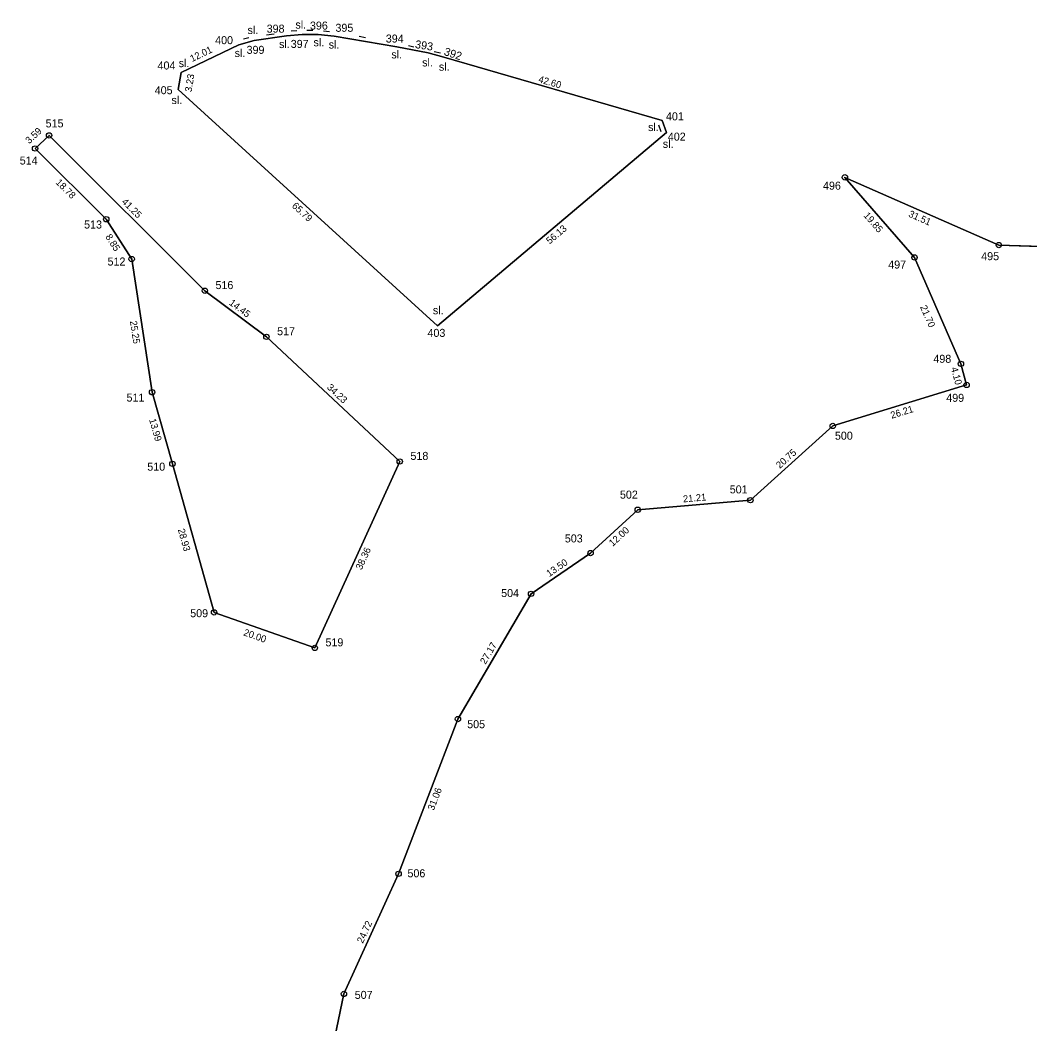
# Model space of a CAD drawing. Extents: x -555170 to -550532, y -1039598 to -1034701.
# Drawn here: x -554680.5 to -554491.3, y -1037842.9 to -1037655 of the extents above; entities that cross this region are included whole.
import ezdxf

# ---------------------------------------------------------------- set-up
doc = ezdxf.new("R2010")
doc.units = 0
for name, color, linetype in [('Vrstva 10', 7, 'Continuous'), ('Vrstva 40', 7, 'Continuous'), ('Vrstva 43', 7, 'Continuous'), ('Vrstva 48', 7, 'Continuous')]:
    doc.layers.add(name, color=color, linetype=linetype)

msp = doc.modelspace()

# ---------------------------------------------------------------- linework, layer by layer
at = {"layer": 'Vrstva 10'}
for p, q in [((-554628.65, -1037657.03), (-554629.67, -1037657.09)), ((-554625.63, -1037656.97), (-554626.76, -1037656.97)), ((-554622.48, -1037657.24), (-554623.65, -1037657.11)), ((-554637.62, -1037658.34), (-554638.61, -1037658.59)), ((-554632.88, -1037657.66), (-554634.28, -1037657.85)), ((-554616.95, -1037658.04), (-554615.74, -1037658.28)), ((-554607.71, -1037659.79), (-554606.7, -1037660)), ((-554602.87, -1037660.9), (-554601.74, -1037661.16)), ((-554560.84, -1037674.63), (-554560.42, -1037675.86))]:
    msp.add_line(p, q, dxfattribs=at)
at = {"layer": 'Vrstva 40'}
for p, q in [((-554636.61, -1037658.83), (-554639.47, -1037659.62)), ((-554630.58, -1037657.95), (-554636.61, -1037658.83)), ((-554627.61, -1037657.69), (-554630.58, -1037657.95)), ((-554624.62, -1037657.74), (-554627.61, -1037657.69)), ((-554621.62, -1037657.99), (-554624.62, -1037657.74)), ((-554609.88, -1037660.03), (-554621.62, -1037657.99)), ((-554639.47, -1037659.62), (-554650.32, -1037664.84)), ((-554604, -1037661.17), (-554609.88, -1037660.03)), ((-554601.06, -1037661.93), (-554604, -1037661.17)), ((-554560.2, -1037673.84), (-554601.06, -1037661.93)), ((-554650.32, -1037664.84), (-554650.84, -1037668.03)), ((-554650.84, -1037668.03), (-554602.26, -1037712.22)), ((-554559.4, -1037676.04), (-554560.2, -1037673.84)), ((-554602.26, -1037712.22), (-554559.4, -1037676.04)), ((-554675.05, -1037676.6), (-554677.67, -1037679.05)), ((-554645.87, -1037705.67), (-554675.05, -1037676.6)), ((-554677.67, -1037679.05), (-554664.33, -1037692.29)), ((-554497.11, -1037697.13), (-554525.95, -1037684.45)), ((-554525.95, -1037684.45), (-554512.91, -1037699.45)), ((-554664.33, -1037692.29), (-554659.57, -1037699.74)), ((-554453.05, -1037698.58), (-554497.11, -1037697.13)), ((-554659.57, -1037699.74), (-554655.75, -1037724.68)), ((-554512.91, -1037699.45), (-554504.21, -1037719.35)), ((-554634.32, -1037714.31), (-554645.87, -1037705.67)), ((-554609.34, -1037737.65), (-554634.32, -1037714.31)), ((-554504.21, -1037719.35), (-554503.14, -1037723.31)), ((-554503.14, -1037723.31), (-554528.22, -1037731)), ((-554655.75, -1037724.68), (-554651.93, -1037738.08)), ((-554528.22, -1037731), (-554543.65, -1037744.89)), ((-554651.93, -1037738.08), (-554644.13, -1037765.9)), ((-554625.26, -1037772.55), (-554609.34, -1037737.65)), ((-554543.65, -1037744.89), (-554564.77, -1037746.69)), ((-554564.77, -1037746.69), (-554573.59, -1037754.79)), ((-554573.59, -1037754.79), (-554584.74, -1037762.42)), ((-554584.74, -1037762.42), (-554598.45, -1037785.86)), ((-554644.13, -1037765.9), (-554625.26, -1037772.55)), ((-554598.45, -1037785.86), (-554609.57, -1037814.85)), ((-554609.57, -1037814.85), (-554619.81, -1037837.33)), ((-554619.81, -1037837.33), (-554624.63, -1037860.46))]:
    msp.add_line(p, q, dxfattribs=at)
at = {"layer": 'Vrstva 43'}
for p, q in [((-554636.61, -1037658.83), (-554636.61, -1037658.83)), ((-554630.58, -1037657.95), (-554630.58, -1037657.95)), ((-554627.61, -1037657.69), (-554627.61, -1037657.69)), ((-554624.62, -1037657.74), (-554624.62, -1037657.74)), ((-554621.62, -1037657.99), (-554621.62, -1037657.99)), ((-554639.47, -1037659.62), (-554639.47, -1037659.62)), ((-554609.88, -1037660.03), (-554609.88, -1037660.03)), ((-554604, -1037661.17), (-554604, -1037661.17)), ((-554601.06, -1037661.93), (-554601.06, -1037661.93)), ((-554650.32, -1037664.84), (-554650.32, -1037664.84)), ((-554650.84, -1037668.03), (-554650.84, -1037668.03)), ((-554560.2, -1037673.84), (-554560.2, -1037673.84)), ((-554559.4, -1037676.04), (-554559.4, -1037676.04)), ((-554675.05, -1037676.6), (-554675.05, -1037676.6)), ((-554677.67, -1037679.05), (-554677.67, -1037679.05)), ((-554525.95, -1037684.45), (-554525.95, -1037684.45)), ((-554664.33, -1037692.29), (-554664.33, -1037692.29)), ((-554497.11, -1037697.13), (-554497.11, -1037697.13)), ((-554659.57, -1037699.74), (-554659.57, -1037699.74)), ((-554512.91, -1037699.45), (-554512.91, -1037699.45)), ((-554645.87, -1037705.67), (-554645.87, -1037705.67)), ((-554602.26, -1037712.22), (-554602.26, -1037712.22)), ((-554634.32, -1037714.31), (-554634.32, -1037714.31)), ((-554504.21, -1037719.35), (-554504.21, -1037719.35)), ((-554503.14, -1037723.31), (-554503.14, -1037723.31)), ((-554655.75, -1037724.68), (-554655.75, -1037724.68)), ((-554528.22, -1037731), (-554528.22, -1037731)), ((-554651.93, -1037738.08), (-554651.93, -1037738.08)), ((-554609.34, -1037737.65), (-554609.34, -1037737.65)), ((-554543.65, -1037744.89), (-554543.65, -1037744.89)), ((-554564.77, -1037746.69), (-554564.77, -1037746.69)), ((-554573.59, -1037754.79), (-554573.59, -1037754.79)), ((-554584.74, -1037762.42), (-554584.74, -1037762.42)), ((-554644.13, -1037765.9), (-554644.13, -1037765.9)), ((-554625.26, -1037772.55), (-554625.26, -1037772.55)), ((-554598.45, -1037785.86), (-554598.45, -1037785.86)), ((-554609.57, -1037814.85), (-554609.57, -1037814.85)), ((-554619.81, -1037837.33), (-554619.81, -1037837.33))]:
    msp.add_line(p, q, dxfattribs=at)
for centre, radius in [((-554675.05, -1037676.6), 0.5), ((-554675.05, -1037676.6), 0.01), ((-554677.67, -1037679.05), 0.5), ((-554677.67, -1037679.05), 0.01), ((-554525.95, -1037684.45), 0.5), ((-554525.95, -1037684.45), 0.01), ((-554664.33, -1037692.29), 0.5), ((-554664.33, -1037692.29), 0.01), ((-554497.11, -1037697.13), 0.5), ((-554497.11, -1037697.13), 0.01), ((-554659.57, -1037699.74), 0.5), ((-554659.57, -1037699.74), 0.01), ((-554512.91, -1037699.45), 0.5), ((-554512.91, -1037699.45), 0.01), ((-554645.87, -1037705.67), 0.5), ((-554645.87, -1037705.67), 0.01), ((-554634.32, -1037714.31), 0.5), ((-554634.32, -1037714.31), 0.01), ((-554504.21, -1037719.36), 0.5), ((-554504.21, -1037719.36), 0.01), ((-554503.14, -1037723.31), 0.5), ((-554503.14, -1037723.31), 0.01), ((-554655.75, -1037724.68), 0.5), ((-554655.75, -1037724.68), 0.01), ((-554528.22, -1037731), 0.5), ((-554528.22, -1037731), 0.01), ((-554651.93, -1037738.08), 0.5), ((-554651.93, -1037738.08), 0.01), ((-554609.34, -1037737.65), 0.5), ((-554609.34, -1037737.65), 0.01), ((-554564.77, -1037746.69), 0.5), ((-554543.65, -1037744.89), 0.5), ((-554543.65, -1037744.89), 0.01), ((-554564.77, -1037746.69), 0.01), ((-554573.59, -1037754.79), 0.5), ((-554573.59, -1037754.79), 0.01), ((-554584.74, -1037762.42), 0.5), ((-554584.74, -1037762.42), 0.01), ((-554644.13, -1037765.9), 0.5), ((-554644.13, -1037765.9), 0.01), ((-554625.26, -1037772.55), 0.5), ((-554625.26, -1037772.55), 0.01), ((-554598.45, -1037785.86), 0.5), ((-554598.45, -1037785.86), 0.01), ((-554609.57, -1037814.85), 0.5), ((-554609.57, -1037814.85), 0.01), ((-554619.81, -1037837.33), 0.5), ((-554619.81, -1037837.33), 0.01)]:
    msp.add_circle(centre, radius, dxfattribs=at)
at = {"layer": 'Vrstva 48'}
for points in [[(-554559.4, -1037676.04), (-554602.26, -1037712.22), (-554650.84, -1037668.03), (-554650.32, -1037664.84), (-554639.47, -1037659.62), (-554636.61, -1037658.83), (-554630.58, -1037657.95), (-554627.61, -1037657.69), (-554624.62, -1037657.74), (-554621.62, -1037657.99), (-554609.88, -1037660.03), (-554604, -1037661.17), (-554601.06, -1037661.93), (-554560.2, -1037673.84), (-554559.4, -1037676.04)], [(-554677.67, -1037679.05), (-554675.05, -1037676.6), (-554645.87, -1037705.67), (-554634.32, -1037714.31), (-554609.34, -1037737.65), (-554625.26, -1037772.55), (-554644.13, -1037765.9), (-554651.93, -1037738.08), (-554655.75, -1037724.68), (-554659.57, -1037699.74), (-554664.33, -1037692.29), (-554677.67, -1037679.05)], [(-554624.63, -1037860.46), (-554619.81, -1037837.33), (-554609.57, -1037814.85), (-554598.45, -1037785.86), (-554584.74, -1037762.42), (-554573.59, -1037754.79), (-554564.77, -1037746.69), (-554543.65, -1037744.89), (-554528.22, -1037731), (-554503.14, -1037723.31), (-554504.21, -1037719.35), (-554512.91, -1037699.45), (-554525.95, -1037684.45), (-554497.11, -1037697.13), (-554453.05, -1037698.58)]]:
    msp.add_lwpolyline(points, dxfattribs=at)

# ---------------------------------------------------------------- texts
at = {"layer": 'Vrstva 10'}
for s, rotation, p in [('12.01', 25.6925, (-554648.26, -1037662.88)), ('3.23', 80.7417, (-554648.35, -1037668.55)), ('42.60', 343.7495, (-554583.48, -1037666.63)), ('3.59', 42.9743, (-554678.76, -1037678.26)), ('18.78', 315.2051, (-554673.92, -1037685.52)), ('41.25', 315.1011, (-554661.53, -1037689.15)), ('65.79', 317.7093, (-554629.65, -1037689.94)), ('19.85', 310.993, (-554522.53, -1037691.65)), ('31.51', 336.259, (-554514.15, -1037691.76)), ('8.85', 302.6109, (-554664.55, -1037695.58)), ('56.13', 40.1692, (-554581.25, -1037697.04)), ('14.45', 323.2228, (-554641.43, -1037708.18)), ('21.70', 293.6041, (-554511.89, -1037708.72)), ('25.25', 278.6999, (-554659.9, -1037711.39)), ('4.10', 285.0804, (-554506.1, -1037720.16)), ('34.23', 316.9368, (-554623.09, -1037723.91)), ('26.21', 17.0357, (-554517.17, -1037729.65)), ('13.99', 285.9074, (-554656.32, -1037729.81)), ('20.75', 42.0111, (-554538.14, -1037739.06)), ('21.21', 4.8668, (-554556.22, -1037745.31)), ('12.00', 42.6039, (-554569.44, -1037753.63)), ('28.93', 285.6616, (-554650.93, -1037750.4)), ('38.36', 65.4845, (-554616.5, -1037758.05)), ('13.50', 34.3697, (-554581.33, -1037759.3)), ('20.00', 340.5953, (-554638.73, -1037770.17)), ('27.17', 59.6813, (-554593.28, -1037775.73)), ('31.06', 69.0015, (-554602.97, -1037803.08)), ('24.72', 65.5193, (-554616.26, -1037827.96))]:
    msp.add_text(s, height=1.3, rotation=rotation, dxfattribs=at).set_placement(p)
at = {"layer": 'Vrstva 43'}
for s, p in [('sl.', (-554628.89, -1037656.61)), ('396', (-554626.17, -1037656.79)), ('sl.', (-554637.86, -1037657.62)), ('398', (-554634.28, -1037657.36)), ('395', (-554621.39, -1037657.2)), ('400', (-554643.93, -1037659.52)), ('sl.', (-554631.96, -1037660.25)), ('397', (-554629.77, -1037660.22)), ('sl.', (-554625.5, -1037659.92)), ('sl.', (-554622.65, -1037660.34)), ('394', (-554611.96, -1037659.22)), ('sl.', (-554640.28, -1037661.93)), ('399', (-554638.04, -1037661.33)), ('sl.', (-554610.92, -1037662.19)), ('404', (-554654.72, -1037664.26)), ('sl.', (-554650.76, -1037663.82)), ('sl.', (-554605.15, -1037663.69)), ('sl.', (-554602.01, -1037664.49)), ('405', (-554655.25, -1037668.89)), ('sl.', (-554652.11, -1037670.73)), ('401', (-554559.47, -1037673.78)), ('515', (-554675.69, -1037675.1)), ('sl.', (-554562.82, -1037675.79)), ('402', (-554559.12, -1037677.58)), ('sl.', (-554560.06, -1037678.93)), ('514', (-554680.54, -1037682.05)), ('496', (-554530.05, -1037686.76)), ('513', (-554668.48, -1037694.03)), ('495', (-554500.41, -1037699.96)), ('512', (-554664.09, -1037700.96)), ('497', (-554517.83, -1037701.53)), ('516', (-554643.87, -1037705.37)), ('sl.', (-554603.14, -1037710.08)), ('517', (-554632.32, -1037714.01)), ('403', (-554604.15, -1037714.32)), ('498', (-554509.37, -1037719.17)), ('511', (-554660.53, -1037726.43)), ('499', (-554506.96, -1037726.48)), ('500', (-554527.82, -1037733.57)), ('518', (-554607.34, -1037737.35)), ('510', (-554656.64, -1037739.37)), ('501', (-554547.52, -1037743.62)), ('502', (-554568.09, -1037744.6)), ('503', (-554578.42, -1037752.8)), ('504', (-554590.35, -1037763.03)), ('509', (-554648.6, -1037766.8)), ('519', (-554623.26, -1037772.25)), ('505', (-554596.71, -1037787.58)), ('506', (-554607.9, -1037815.49)), ('507', (-554617.78, -1037838.26))]:
    msp.add_text(s, height=1.5, dxfattribs=at).set_placement(p)
for s, rotation, p in [('393', 351, (-554606.55, -1037660.23)), ('392', 342, (-554601.19, -1037661.52))]:
    msp.add_text(s, height=1.5, rotation=rotation, dxfattribs=at).set_placement(p)

doc.saveas('drawing.dxf')
